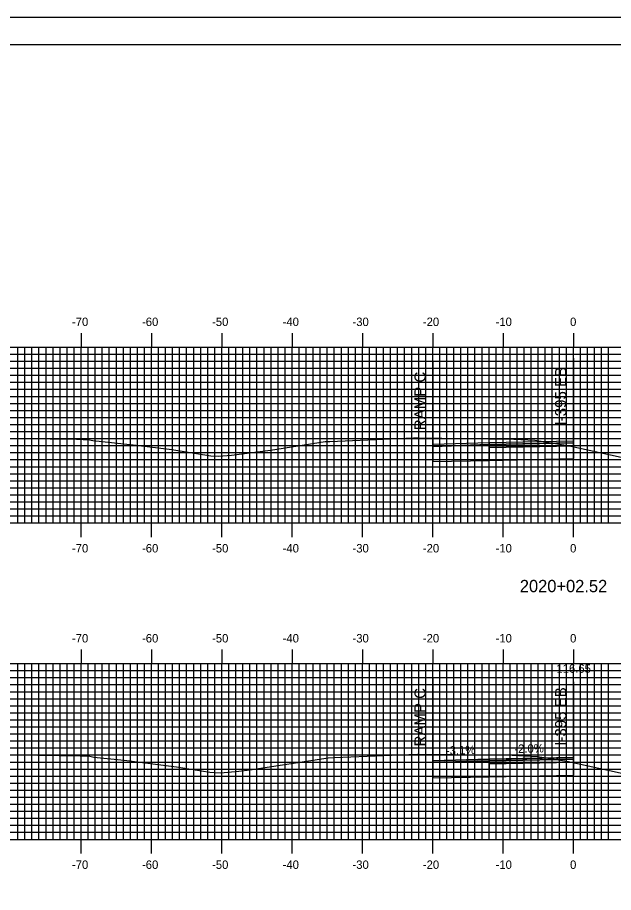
# Model space of a CAD drawing. Extents: x 855468 to 855811, y 366605 to 366825.
# Drawn here: x 855554.5 to 855639.3, y 366700.5 to 366824.9 of the extents above; entities that cross this region are included whole.
import ezdxf

# ---------------------------------------------------------------- set-up
doc = ezdxf.new("R2010")
doc.units = 0
for name, color, linetype in [('ANNOTATION', 7, 'Continuous'), ('BORDER', 7, 'Continuous'), ('D_Roadway_Centerline', 7, 'Continuous'), ('D_Roadway_Centerline_Text', 7, 'Continuous'), ('D_Roadway_Edge_Shoulder', 7, 'Continuous'), ('D_Roadway_Edge_TW', 7, 'Continuous'), ('D_Roadway_Pavement', 7, 'Continuous'), ('D_Roadway_SubGrade', 7, 'Continuous'), ('H_V ANNOTATION', 7, 'Continuous'), ('M_Roadway_Centerline', 7, 'Continuous'), ('MAJOR', 7, 'Continuous'), ('MINOR', 7, 'Continuous'), ('PLOT BOUNDARY', 7, 'Continuous'), ('S_Roadway_Centerline', 7, 'Continuous')]:
    doc.layers.add(name, color=color, linetype=linetype)

msp = doc.modelspace()

# ---------------------------------------------------------------- linework, layer by layer
at = {"layer": 'BORDER'}
msp.add_lwpolyline([(855483.98, 366611.06), (855803.98, 366611.06), (855803.98, 366821.06), (855483.98, 366821.06)], close=True, dxfattribs=at)
at = {"layer": 'D_Roadway_Centerline'}
msp.add_lwpolyline([(855613.58, 366719.22), (855621.58, 366719.47), (855624.74, 366719.53), (855633.58, 366719.71), (855633.58, 366719.71), (855633.58, 366719.71)], dxfattribs=at)
at = {"layer": 'D_Roadway_Edge_Shoulder'}
for points in [[(855621.58, 366764.46), (855613.58, 366764.2), (855613.58, 366763.95), (855621.58, 366764.21)], [(855633.58, 366764.7), (855633.58, 366764.7), (855633.58, 366764.45), (855633.58, 366764.45)], [(855621.58, 366719.47), (855613.58, 366719.22), (855613.58, 366718.97), (855621.58, 366719.22)], [(855633.58, 366719.71), (855633.58, 366719.71), (855633.58, 366719.46), (855633.58, 366719.46)]]:
    msp.add_lwpolyline(points, close=True, dxfattribs=at)
at = {"layer": 'D_Roadway_Edge_TW'}
for points in [[(855633.58, 366764.7), (855621.58, 366764.46), (855621.58, 366764.21), (855633.58, 366764.45)], [(855633.58, 366719.71), (855621.58, 366719.47), (855621.58, 366719.22), (855633.58, 366719.46)]]:
    msp.add_lwpolyline(points, close=True, dxfattribs=at)
for points in [[(855621.58, 366764.46), (855621.58, 366764.21)], [(855621.58, 366719.47), (855621.58, 366719.22)]]:
    msp.add_lwpolyline(points, dxfattribs=at)
at = {"layer": 'D_Roadway_Pavement'}
for points in [[(855633.58, 366764.45), (855621.58, 366764.21), (855621.58, 366763.79), (855633.58, 366764.03)], [(855633.58, 366764.45), (855633.58, 366764.45), (855633.58, 366764.03), (855633.58, 366764.03)], [(855633.58, 366719.46), (855621.58, 366719.22), (855621.58, 366718.8), (855633.58, 366719.04)], [(855633.58, 366719.46), (855633.58, 366719.46), (855633.58, 366719.04), (855633.58, 366719.04)]]:
    msp.add_lwpolyline(points, close=True, dxfattribs=at)
for points in [[(855621.58, 366764.21), (855621.58, 366763.79)], [(855621.58, 366764.21), (855621.58, 366763.79)], [(855621.58, 366764.21), (855621.58, 366763.79)], [(855621.58, 366719.22), (855621.58, 366718.8)], [(855621.58, 366719.22), (855621.58, 366718.8)], [(855621.58, 366719.22), (855621.58, 366718.8)]]:
    msp.add_lwpolyline(points, dxfattribs=at)
at = {"layer": 'D_Roadway_SubGrade'}
for p, q in [((855633.58, 366776.5), (855633.58, 366762.2)), ((855613.58, 366776.01), (855613.58, 366761.8)), ((855613.58, 366731.03), (855613.58, 366716.81)), ((855633.58, 366730.48), (855633.58, 366717.21))]:
    msp.add_line(p, q, dxfattribs=at)
for points in [[(855621.58, 366763.79), (855621.58, 366764.21), (855613.58, 366763.95), (855613.58, 366764.2), (855613.58, 366761.8), (855621.58, 366761.96)], [(855633.58, 366764.03), (855621.58, 366763.79), (855621.58, 366761.96), (855633.58, 366762.2)], [(855633.58, 366764.03), (855633.58, 366764.03), (855633.58, 366764.45), (855633.58, 366764.7), (855633.58, 366762.2), (855633.58, 366762.2)], [(855621.58, 366718.8), (855621.58, 366719.22), (855613.58, 366718.97), (855613.58, 366719.22), (855613.58, 366716.81), (855621.58, 366716.97)], [(855633.58, 366719.04), (855621.58, 366718.8), (855621.58, 366716.97), (855633.58, 366717.21)]]:
    msp.add_lwpolyline(points, close=True, dxfattribs=at)
for points in [[(855621.58, 366763.79), (855621.58, 366761.96)], [(855633.58, 366717.21), (855633.58, 366719.04), (855633.58, 366719.04), (855633.58, 366719.46), (855633.58, 366719.71), (855633.58, 366717.21)], [(855621.58, 366718.8), (855621.58, 366716.97)]]:
    msp.add_lwpolyline(points, dxfattribs=at)
at = {"layer": 'MAJOR'}
for p, q in [((855563.58, 366780.06), (855563.58, 366778.06)), ((855573.58, 366780.06), (855573.58, 366778.06)), ((855583.58, 366780.06), (855583.58, 366778.06)), ((855593.58, 366780.06), (855593.58, 366778.06)), ((855603.58, 366780.06), (855603.58, 366778.06)), ((855613.58, 366780.06), (855613.58, 366778.06)), ((855623.58, 366780.06), (855623.58, 366778.06)), ((855633.58, 366780.06), (855633.58, 366778.06)), ((855493.58, 366778.06), (855773.58, 366778.06)), ((855493.58, 366778.06), (855773.58, 366778.06)), ((855563.58, 366753.06), (855563.58, 366778.06)), ((855573.58, 366753.06), (855573.58, 366778.06)), ((855583.58, 366753.06), (855583.58, 366778.06)), ((855593.58, 366753.06), (855593.58, 366778.06)), ((855603.58, 366753.06), (855603.58, 366778.06)), ((855613.58, 366753.06), (855613.58, 366778.06)), ((855623.58, 366753.06), (855623.58, 366778.06)), ((855633.58, 366753.06), (855633.58, 366778.06)), ((855493.58, 366773.06), (855773.58, 366773.06)), ((855493.58, 366768.06), (855773.58, 366768.06)), ((855493.58, 366763.06), (855773.58, 366763.06)), ((855493.58, 366758.06), (855773.58, 366758.06)), ((855493.58, 366753.06), (855773.58, 366753.06)), ((855493.58, 366753.06), (855773.58, 366753.06)), ((855563.58, 366751.05), (855563.58, 366753.06)), ((855573.58, 366751.05), (855573.58, 366753.06)), ((855583.58, 366751.05), (855583.58, 366753.06)), ((855593.58, 366751.05), (855593.58, 366753.06)), ((855603.58, 366751.05), (855603.58, 366753.06)), ((855613.58, 366751.05), (855613.58, 366753.06)), ((855623.58, 366751.05), (855623.58, 366753.06)), ((855633.58, 366751.05), (855633.58, 366753.06)), ((855563.58, 366735.06), (855563.58, 366733.06)), ((855573.58, 366735.06), (855573.58, 366733.06)), ((855583.58, 366735.06), (855583.58, 366733.06)), ((855593.58, 366735.06), (855593.58, 366733.06)), ((855603.58, 366735.06), (855603.58, 366733.06)), ((855613.58, 366735.06), (855613.58, 366733.06)), ((855623.58, 366735.06), (855623.58, 366733.06)), ((855633.58, 366735.06), (855633.58, 366733.06)), ((855493.58, 366733.06), (855773.58, 366733.06)), ((855493.58, 366733.06), (855773.58, 366733.06)), ((855563.58, 366708.06), (855563.58, 366733.06)), ((855573.58, 366708.06), (855573.58, 366733.06)), ((855583.58, 366708.06), (855583.58, 366733.06)), ((855593.58, 366708.06), (855593.58, 366733.06)), ((855603.58, 366708.06), (855603.58, 366733.06)), ((855613.58, 366708.06), (855613.58, 366733.06)), ((855623.58, 366708.06), (855623.58, 366733.06)), ((855633.58, 366708.06), (855633.58, 366733.06)), ((855493.58, 366728.06), (855773.58, 366728.06)), ((855493.58, 366723.06), (855773.58, 366723.06)), ((855493.58, 366718.06), (855773.58, 366718.06)), ((855493.58, 366713.06), (855773.58, 366713.06)), ((855493.58, 366708.06), (855773.58, 366708.06)), ((855493.58, 366708.06), (855773.58, 366708.06)), ((855563.58, 366706.05), (855563.58, 366708.06)), ((855573.58, 366706.05), (855573.58, 366708.06)), ((855583.58, 366706.05), (855583.58, 366708.06)), ((855593.58, 366706.05), (855593.58, 366708.06)), ((855603.58, 366706.05), (855603.58, 366708.06)), ((855613.58, 366706.05), (855613.58, 366708.06)), ((855623.58, 366706.05), (855623.58, 366708.06)), ((855633.58, 366706.05), (855633.58, 366708.06))]:
    msp.add_line(p, q, dxfattribs=at)
at = {"layer": 'MINOR'}
for p, q in [((855554.58, 366753.06), (855554.58, 366778.06)), ((855555.58, 366753.06), (855555.58, 366778.06)), ((855556.58, 366753.06), (855556.58, 366778.06)), ((855557.58, 366753.06), (855557.58, 366778.06)), ((855558.58, 366753.06), (855558.58, 366778.06)), ((855559.58, 366753.06), (855559.58, 366778.06)), ((855560.58, 366753.06), (855560.58, 366778.06)), ((855561.58, 366753.06), (855561.58, 366778.06)), ((855562.58, 366753.06), (855562.58, 366778.06)), ((855564.58, 366753.06), (855564.58, 366778.06)), ((855565.58, 366753.06), (855565.58, 366778.06)), ((855566.58, 366753.06), (855566.58, 366778.06)), ((855567.58, 366753.06), (855567.58, 366778.06)), ((855568.58, 366753.06), (855568.58, 366778.06)), ((855569.58, 366753.06), (855569.58, 366778.06)), ((855570.58, 366753.06), (855570.58, 366778.06)), ((855571.58, 366753.06), (855571.58, 366778.06)), ((855572.58, 366753.06), (855572.58, 366778.06)), ((855574.58, 366753.06), (855574.58, 366778.06)), ((855575.58, 366753.06), (855575.58, 366778.06)), ((855576.58, 366753.06), (855576.58, 366778.06)), ((855577.58, 366753.06), (855577.58, 366778.06)), ((855578.58, 366753.06), (855578.58, 366778.06)), ((855579.58, 366753.06), (855579.58, 366778.06)), ((855580.58, 366753.06), (855580.58, 366778.06)), ((855581.58, 366753.06), (855581.58, 366778.06)), ((855582.58, 366753.06), (855582.58, 366778.06)), ((855584.58, 366753.06), (855584.58, 366778.06)), ((855585.58, 366753.06), (855585.58, 366778.06)), ((855586.58, 366753.06), (855586.58, 366778.06)), ((855587.58, 366753.06), (855587.58, 366778.06)), ((855588.58, 366753.06), (855588.58, 366778.06)), ((855589.58, 366753.06), (855589.58, 366778.06)), ((855590.58, 366753.06), (855590.58, 366778.06)), ((855591.58, 366753.06), (855591.58, 366778.06)), ((855592.58, 366753.06), (855592.58, 366778.06)), ((855594.58, 366753.06), (855594.58, 366778.06)), ((855595.58, 366753.06), (855595.58, 366778.06)), ((855596.58, 366753.06), (855596.58, 366778.06)), ((855597.58, 366753.06), (855597.58, 366778.06)), ((855598.58, 366753.06), (855598.58, 366778.06)), ((855599.58, 366753.06), (855599.58, 366778.06)), ((855600.58, 366753.06), (855600.58, 366778.06)), ((855601.58, 366753.06), (855601.58, 366778.06)), ((855602.58, 366753.06), (855602.58, 366778.06)), ((855604.58, 366753.06), (855604.58, 366778.06)), ((855605.58, 366753.06), (855605.58, 366778.06)), ((855606.58, 366753.06), (855606.58, 366778.06)), ((855607.58, 366753.06), (855607.58, 366778.06)), ((855608.58, 366753.06), (855608.58, 366778.06)), ((855609.58, 366753.06), (855609.58, 366778.06)), ((855610.58, 366753.06), (855610.58, 366778.06)), ((855611.58, 366753.06), (855611.58, 366778.06)), ((855612.58, 366753.06), (855612.58, 366778.06)), ((855614.58, 366753.06), (855614.58, 366778.06)), ((855615.58, 366753.06), (855615.58, 366778.06)), ((855616.58, 366753.06), (855616.58, 366778.06)), ((855617.58, 366753.06), (855617.58, 366778.06)), ((855618.58, 366753.06), (855618.58, 366778.06)), ((855619.58, 366753.06), (855619.58, 366778.06)), ((855620.58, 366753.06), (855620.58, 366778.06)), ((855621.58, 366753.06), (855621.58, 366778.06)), ((855622.58, 366753.06), (855622.58, 366778.06)), ((855624.58, 366753.06), (855624.58, 366778.06)), ((855625.58, 366753.06), (855625.58, 366778.06)), ((855626.58, 366753.06), (855626.58, 366778.06)), ((855627.58, 366753.06), (855627.58, 366778.06)), ((855628.58, 366753.06), (855628.58, 366778.06)), ((855629.58, 366753.06), (855629.58, 366778.06)), ((855630.58, 366753.06), (855630.58, 366778.06)), ((855631.58, 366753.06), (855631.58, 366778.06)), ((855632.58, 366753.06), (855632.58, 366778.06)), ((855634.58, 366753.06), (855634.58, 366778.06)), ((855635.58, 366753.06), (855635.58, 366778.06)), ((855636.58, 366753.06), (855636.58, 366778.06)), ((855637.58, 366753.06), (855637.58, 366778.06)), ((855638.58, 366753.06), (855638.58, 366778.06)), ((855493.58, 366777.06), (855773.58, 366777.06)), ((855493.58, 366776.06), (855773.58, 366776.06)), ((855493.58, 366775.06), (855773.58, 366775.06)), ((855493.58, 366774.06), (855773.58, 366774.06)), ((855493.58, 366772.06), (855773.58, 366772.06)), ((855493.58, 366771.06), (855773.58, 366771.06)), ((855493.58, 366770.06), (855773.58, 366770.06)), ((855493.58, 366769.06), (855773.58, 366769.06)), ((855493.58, 366767.06), (855773.58, 366767.06)), ((855493.58, 366766.06), (855773.58, 366766.06)), ((855493.58, 366765.06), (855773.58, 366765.06)), ((855493.58, 366764.06), (855773.58, 366764.06)), ((855493.58, 366762.06), (855773.58, 366762.06)), ((855493.58, 366761.06), (855773.58, 366761.06)), ((855493.58, 366760.06), (855773.58, 366760.06)), ((855493.58, 366759.06), (855773.58, 366759.06)), ((855493.58, 366757.06), (855773.58, 366757.06)), ((855493.58, 366756.06), (855773.58, 366756.06)), ((855493.58, 366755.06), (855773.58, 366755.06)), ((855493.58, 366754.06), (855773.58, 366754.06)), ((855554.58, 366708.06), (855554.58, 366733.06)), ((855555.58, 366708.06), (855555.58, 366733.06)), ((855556.58, 366708.06), (855556.58, 366733.06)), ((855557.58, 366708.06), (855557.58, 366733.06)), ((855558.58, 366708.06), (855558.58, 366733.06)), ((855559.58, 366708.06), (855559.58, 366733.06)), ((855560.58, 366708.06), (855560.58, 366733.06)), ((855561.58, 366708.06), (855561.58, 366733.06)), ((855562.58, 366708.06), (855562.58, 366733.06)), ((855564.58, 366708.06), (855564.58, 366733.06)), ((855565.58, 366708.06), (855565.58, 366733.06)), ((855566.58, 366708.06), (855566.58, 366733.06)), ((855567.58, 366708.06), (855567.58, 366733.06)), ((855568.58, 366708.06), (855568.58, 366733.06)), ((855569.58, 366708.06), (855569.58, 366733.06)), ((855570.58, 366708.06), (855570.58, 366733.06)), ((855571.58, 366708.06), (855571.58, 366733.06)), ((855572.58, 366708.06), (855572.58, 366733.06)), ((855574.58, 366708.06), (855574.58, 366733.06)), ((855575.58, 366708.06), (855575.58, 366733.06)), ((855576.58, 366708.06), (855576.58, 366733.06)), ((855577.58, 366708.06), (855577.58, 366733.06)), ((855578.58, 366708.06), (855578.58, 366733.06)), ((855579.58, 366708.06), (855579.58, 366733.06)), ((855580.58, 366708.06), (855580.58, 366733.06)), ((855581.58, 366708.06), (855581.58, 366733.06)), ((855582.58, 366708.06), (855582.58, 366733.06)), ((855584.58, 366708.06), (855584.58, 366733.06)), ((855585.58, 366708.06), (855585.58, 366733.06)), ((855586.58, 366708.06), (855586.58, 366733.06)), ((855587.58, 366708.06), (855587.58, 366733.06)), ((855588.58, 366708.06), (855588.58, 366733.06)), ((855589.58, 366708.06), (855589.58, 366733.06)), ((855590.58, 366708.06), (855590.58, 366733.06)), ((855591.58, 366708.06), (855591.58, 366733.06)), ((855592.58, 366708.06), (855592.58, 366733.06)), ((855594.58, 366708.06), (855594.58, 366733.06)), ((855595.58, 366708.06), (855595.58, 366733.06)), ((855596.58, 366708.06), (855596.58, 366733.06)), ((855597.58, 366708.06), (855597.58, 366733.06)), ((855598.58, 366708.06), (855598.58, 366733.06)), ((855599.58, 366708.06), (855599.58, 366733.06)), ((855600.58, 366708.06), (855600.58, 366733.06)), ((855601.58, 366708.06), (855601.58, 366733.06)), ((855602.58, 366708.06), (855602.58, 366733.06)), ((855604.58, 366708.06), (855604.58, 366733.06)), ((855605.58, 366708.06), (855605.58, 366733.06)), ((855606.58, 366708.06), (855606.58, 366733.06)), ((855607.58, 366708.06), (855607.58, 366733.06)), ((855608.58, 366708.06), (855608.58, 366733.06)), ((855609.58, 366708.06), (855609.58, 366733.06)), ((855610.58, 366708.06), (855610.58, 366733.06)), ((855611.58, 366708.06), (855611.58, 366733.06)), ((855612.58, 366708.06), (855612.58, 366733.06)), ((855614.58, 366708.06), (855614.58, 366733.06)), ((855615.58, 366708.06), (855615.58, 366733.06)), ((855616.58, 366708.06), (855616.58, 366733.06)), ((855617.58, 366708.06), (855617.58, 366733.06)), ((855618.58, 366708.06), (855618.58, 366733.06)), ((855619.58, 366708.06), (855619.58, 366733.06)), ((855620.58, 366708.06), (855620.58, 366733.06)), ((855621.58, 366708.06), (855621.58, 366733.06)), ((855622.58, 366708.06), (855622.58, 366733.06)), ((855624.58, 366708.06), (855624.58, 366733.06)), ((855625.58, 366708.06), (855625.58, 366733.06)), ((855626.58, 366708.06), (855626.58, 366733.06)), ((855627.58, 366708.06), (855627.58, 366733.06)), ((855628.58, 366708.06), (855628.58, 366733.06)), ((855629.58, 366708.06), (855629.58, 366733.06)), ((855630.58, 366708.06), (855630.58, 366733.06)), ((855631.58, 366708.06), (855631.58, 366733.06)), ((855632.58, 366708.06), (855632.58, 366733.06)), ((855634.58, 366708.06), (855634.58, 366733.06)), ((855635.58, 366708.06), (855635.58, 366733.06)), ((855636.58, 366708.06), (855636.58, 366733.06)), ((855637.58, 366708.06), (855637.58, 366733.06)), ((855638.58, 366708.06), (855638.58, 366733.06)), ((855493.58, 366732.06), (855773.58, 366732.06)), ((855493.58, 366731.06), (855773.58, 366731.06)), ((855493.58, 366730.06), (855773.58, 366730.06)), ((855493.58, 366729.06), (855773.58, 366729.06)), ((855493.58, 366727.06), (855773.58, 366727.06)), ((855493.58, 366726.06), (855773.58, 366726.06)), ((855493.58, 366725.06), (855773.58, 366725.06)), ((855493.58, 366724.06), (855773.58, 366724.06)), ((855493.58, 366722.06), (855773.58, 366722.06)), ((855493.58, 366721.06), (855773.58, 366721.06)), ((855493.58, 366720.06), (855773.58, 366720.06)), ((855493.58, 366719.06), (855773.58, 366719.06)), ((855493.58, 366717.06), (855773.58, 366717.06)), ((855493.58, 366716.06), (855773.58, 366716.06)), ((855493.58, 366715.06), (855773.58, 366715.06)), ((855493.58, 366714.06), (855773.58, 366714.06)), ((855493.58, 366712.06), (855773.58, 366712.06)), ((855493.58, 366711.06), (855773.58, 366711.06)), ((855493.58, 366710.06), (855773.58, 366710.06)), ((855493.58, 366709.06), (855773.58, 366709.06))]:
    msp.add_line(p, q, dxfattribs=at)
at = {"layer": 'PLOT BOUNDARY'}
msp.add_lwpolyline([(855467.8, 366604.94), (855807.8, 366604.94), (855807.8, 366824.94), (855467.8, 366824.94)], close=True, dxfattribs=at)
at = {"layer": 'S_Roadway_Centerline'}
for points in [[(855551.67, 366765.1), (855562.93, 366764.96), (855564.76, 366764.88), (855565.22, 366764.77), (855571.39, 366764.13), (855576.47, 366763.48), (855582, 366762.62), (855583.09, 366762.53), (855584.98, 366762.69), (855590.52, 366763.43), (855598.3, 366764.62), (855598.94, 366764.65), (855610.82, 366765.14), (855611.03, 366765.15), (855611.05, 366765.15), (855611.46, 366765.14), (855625.09, 366764.95), (855628.09, 366764.81), (855632.79, 366764.07), (855637.35, 366763.08), (855646.02, 366761.18)], [(855554.41, 366720.07), (855563.42, 366719.96), (855564.83, 366719.9), (855565.37, 366719.77), (855569.7, 366719.32), (855577.15, 366718.37), (855581.86, 366717.63), (855583.37, 366717.52), (855586.01, 366717.74), (855587.57, 366717.94), (855598.68, 366719.65), (855599.59, 366719.69), (855608.91, 366720.07), (855611.41, 366720.17), (855611.66, 366720.18), (855616.74, 366720.12), (855624.86, 366720.01), (855628.49, 366719.83), (855632.65, 366719.18), (855638.71, 366717.86), (855646.47, 366716.16)]]:
    msp.add_lwpolyline(points, dxfattribs=at)

# ---------------------------------------------------------------- texts
at = {"layer": 'ANNOTATION'}
for s, height, rotation, p in [('RAMP C', 1.6, 90, (855612.57, 366766.25)), ('I-395 EB', 1.6, 90, (855632.57, 366766.92)), ('RAMP C', 1.6, 90, (855612.57, 366721.27)), ('I-395 EB', 1.6, 90, (855632.57, 366721.37)), ('-3.1%', 1.2, 1.7613, (855615.46, 366720.08)), ('-2.0%', 1.2, 1.1457, (855625.19, 366720.34))]:
    msp.add_text(s, height=height, rotation=rotation, dxfattribs=at).set_placement(p)
at = {"layer": 'D_Roadway_Centerline_Text'}
msp.add_text('116.65', height=1.2, dxfattribs=at).set_placement((855631.16, 366731.75))
at = {"layer": 'H_V ANNOTATION'}
for s, height, p in [('-70', 1.2, (855562.27, 366781.06)), ('-60', 1.2, (855572.23, 366781.06)), ('-50', 1.2, (855582.19, 366781.06)), ('-40', 1.2, (855592.23, 366781.06)), ('-30', 1.2, (855602.16, 366781.06)), ('-20', 1.2, (855612.17, 366781.06)), ('-10', 1.2, (855622.51, 366781.06)), ('0', 1.2, (855633.1, 366781.06)), ('-70', 1.2, (855562.27, 366748.86)), ('-60', 1.2, (855572.23, 366748.86)), ('-50', 1.2, (855582.19, 366748.86)), ('-40', 1.2, (855592.23, 366748.86)), ('-30', 1.2, (855602.16, 366748.86)), ('-20', 1.2, (855612.17, 366748.86)), ('-10', 1.2, (855622.51, 366748.86)), ('0', 1.2, (855633.1, 366748.86)), ('2020+02.52', 1.75, (855625.96, 366743.21)), ('-70', 1.2, (855562.27, 366736.06)), ('-60', 1.2, (855572.23, 366736.06)), ('-50', 1.2, (855582.19, 366736.06)), ('-40', 1.2, (855592.23, 366736.06)), ('-30', 1.2, (855602.16, 366736.06)), ('-20', 1.2, (855612.17, 366736.06)), ('-10', 1.2, (855622.51, 366736.06)), ('0', 1.2, (855633.1, 366736.06)), ('-70', 1.2, (855562.27, 366703.86)), ('-60', 1.2, (855572.23, 366703.86)), ('-50', 1.2, (855582.19, 366703.86)), ('-40', 1.2, (855592.23, 366703.86)), ('-30', 1.2, (855602.16, 366703.86)), ('-20', 1.2, (855612.17, 366703.86)), ('-10', 1.2, (855622.51, 366703.86)), ('0', 1.2, (855633.1, 366703.86))]:
    msp.add_text(s, height=height, dxfattribs=at).set_placement(p)
at = {"layer": 'M_Roadway_Centerline'}
for s, p in [('C', (855611.02, 366765.15)), ('L', (855611.03, 366765.14)), ('C', (855611.41, 366720.17)), ('L', (855611.41, 366720.16))]:
    msp.add_text(s, height=0.0146, dxfattribs=at).set_placement(p)

doc.saveas('drawing.dxf')
